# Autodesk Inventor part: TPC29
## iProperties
Shininess: 64.0
Length Units: 11272
Angle Units: 11279
Time Units: 11290
Mass Units: 11286
Length Display Precision: 3
Angle Display Precision: 2
Compacted: True
Part Number: TPC29
Document SubType Name: Modeling
Created: 2004-08
Designer: Lori
Manufacturer: Standard
Standards Organization: Custom
Material: Steel, Mild
Density: 0.0
Volumn: 0.0
Area: 0.0
PropertySet Name: Model Information
Control State: 0
Master: False
Checked Out: False
Author: Lori
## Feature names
1. Base1
